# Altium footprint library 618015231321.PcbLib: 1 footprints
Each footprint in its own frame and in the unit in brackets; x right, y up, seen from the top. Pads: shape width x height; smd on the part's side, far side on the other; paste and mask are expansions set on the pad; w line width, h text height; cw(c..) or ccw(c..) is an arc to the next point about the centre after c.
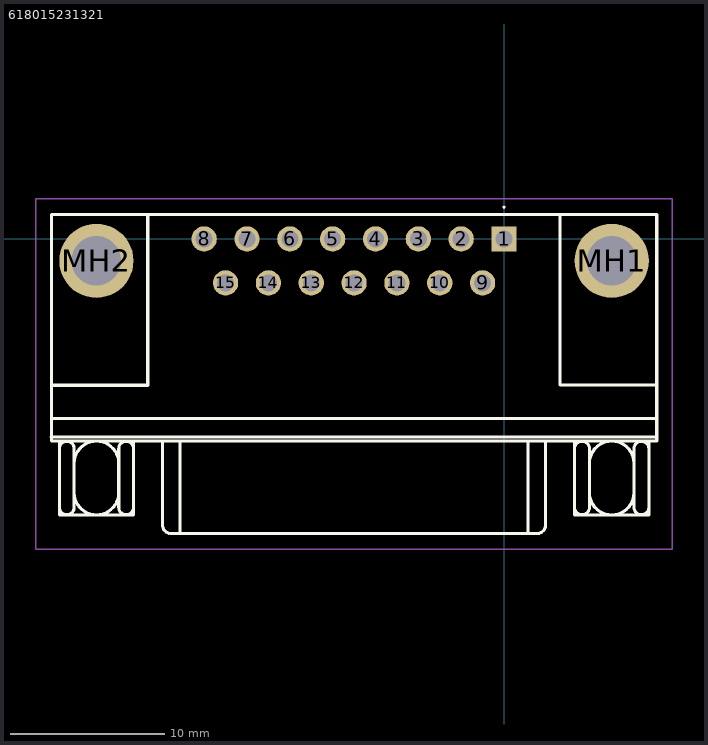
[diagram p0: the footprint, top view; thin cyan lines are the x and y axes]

## 618015231321 [mm]
pads (17):
  rect 1.635x1.635 hole 1.09: 1(0,0)
  round 1.635 hole 1.09: 2(-2.77,0) 3(-5.54,0) 4(-8.31,0) 5(-11.08,0) 6(-13.85,0) 7(-16.62,0) 8(-19.39,0) 9(-1.385,-2.84) 10(-4.155,-2.84) 11(-6.925,-2.84) 12(-9.695,-2.84) 13(-12.465,-2.84) 14(-15.235,-2.84) 15(-18.005,-2.84)
  round 4.8 hole 3.2: MH1(6.965,-1.42) MH2(-26.355,-1.42)
Top Overlay:
  lines w0.1: 0,2 cw(c0,2.05) 0,2.1 ; 0,2 0,2 ; 0,2 ccw(c0,2.05) 0,2.1 ; 0,2.1 0,2.1
  lines w0.2: -29.275,-12.82 9.875,-12.82 ; -29.265,-11.62 9.875,-11.62 ; -29.265,-9.46 -23.035,-9.46 -23.035,1.59 ; -28.755,-17.38 -28.755,-17.86 -23.955,-17.86 -23.955,-13.06 -28.755,-13.06 -28.755,-13.3 -28.755,-13.54 ; -27.795,-16.26 -27.795,-16.41 ; -27.795,-14.66 -27.795,-14.51 ; -24.915,-16.26 -24.915,-16.41 cw(c-26.355,-16.41) -27.795,-16.41 ; -24.915,-14.66 -24.915,-14.51 ccw(c-26.355,-14.51) -27.795,-14.51 ; -22.076,-18.561 ccw(c-21.512,-18.494) -21.512,-19.061 ; -22.075,-18.56 -22.075,-13.06 ; -20.95,-19.06 -20.95,-13.06 ; 1.56,-19.06 1.56,-13.06 ; 2.685,-18.56 2.685,-13.06 ; 2.686,-18.561 cw(c2.123,-18.494) 2.123,-19.061 ; 3.627,1.585 3.627,-9.455 9.875,-9.455 ; 4.565,-15.94 4.565,-17.86 9.365,-17.86 9.365,-13.06 4.565,-13.06 4.565,-13.56 ; 5.525,-16.26 5.525,-16.41 ; 5.525,-14.66 5.525,-14.51 ; 8.405,-16.26 8.405,-16.41 cw(c6.965,-16.41) 5.525,-16.41 ; 8.405,-14.66 8.405,-14.51 ccw(c6.965,-14.51) 5.525,-14.51 ; -29.265,-13.06 9.875,-13.06 ; -29.265,-13.06 -29.265,1.59 9.875,1.59 9.875,-13.06 ; -29.265,-13.06 9.875,-13.06 ; -28.755,-17.36 -28.755,-17.36 ; -28.755,-17.36 ccw(c-28.275,-17.36) -27.795,-17.36 -27.795,-13.56 ; -28.755,-17.36 -28.755,-13.56 cw(c-28.275,-13.56) -27.795,-13.56 ; -27.795,-16.41 -27.795,-16.41 ; -27.795,-14.51 -27.795,-14.51 ; -27.795,-13.56 -27.795,-13.56 ; -24.915,-13.56 -24.915,-13.56 ; -24.915,-13.56 cw(c-24.435,-13.56) -23.955,-13.56 -23.955,-17.36 ; -24.915,-13.56 -24.915,-17.36 ccw(c-24.435,-17.36) -23.955,-17.36 ; -23.955,-17.36 -23.955,-17.36 ; -21.512,-19.06 -9.695,-19.06 2.122,-19.06 ; -21.512,-19.06 -21.512,-19.06 ; 2.122,-19.06 2.122,-19.06 ; 4.565,-13.56 4.565,-13.56 ; 4.565,-13.56 cw(c5.045,-13.56) 5.525,-13.56 5.525,-17.36 ; 4.565,-13.56 4.565,-17.36 ccw(c5.045,-17.36) 5.525,-17.36 ; 5.525,-17.36 5.525,-17.36 ; 5.525,-16.41 5.525,-16.41 ; 5.525,-14.51 5.525,-14.51 ; 8.405,-13.56 8.405,-13.56 ; 8.405,-13.56 cw(c8.885,-13.56) 9.365,-13.56 9.365,-17.36 ; 8.405,-13.56 8.405,-17.36 ccw(c8.885,-17.36) 9.365,-17.36 ; 9.365,-17.36 9.365,-17.36
Mechanical 15:
  lines w0.1: -22.076,-18.561 ccw(c-21.512,-18.494) -21.512,-19.061 ; -22.075,-18.56 -22.075,-13.06 ; -20.95,-19.06 -20.95,-13.06 ; 1.56,-19.06 1.56,-13.06 ; 2.685,-18.56 2.685,-13.06 ; 2.686,-18.561 cw(c2.123,-18.494) 2.123,-19.061 ; -21.512,-19.06 -9.695,-19.06 2.122,-19.06 ; -21.512,-19.06 -21.512,-19.06 ; 2.122,-19.06 2.122,-19.06 ; -29.265,-13.06 9.875,-13.06 9.875,1.59 -29.265,1.59 -29.265,-13.06
Mechanical 20:
  lines w0.1: -30.275,-20.06 10.875,-20.06 10.875,2.59 -30.275,2.59 -30.275,-20.06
